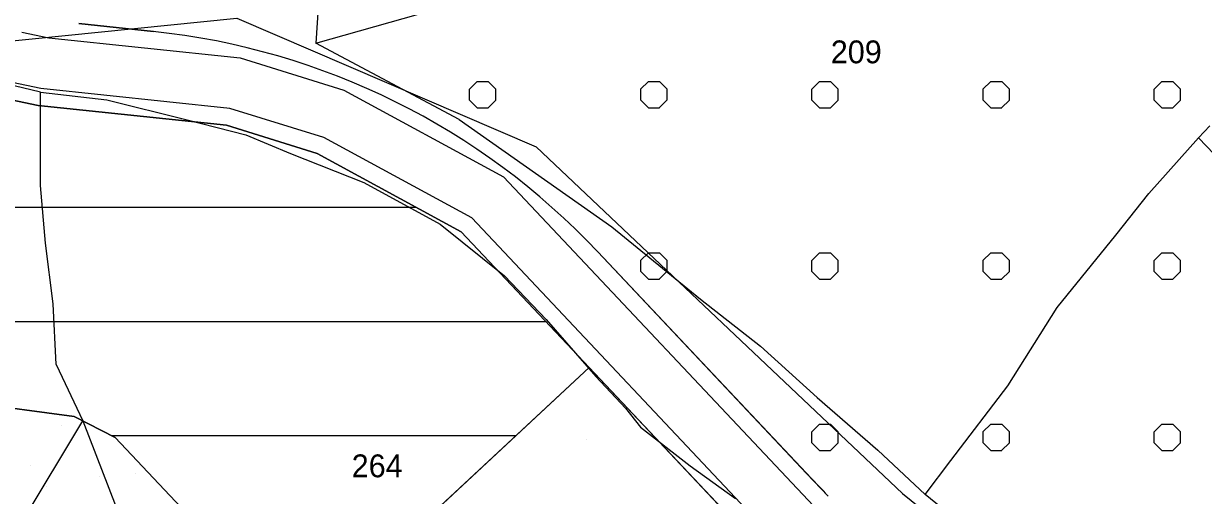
# Model space of a CAD drawing. Extents: x 410727 to 412947, y 4463506 to 4466382.
# Drawn here: x 411364.1 to 411570.9, y 4465926.9 to 4466009.6 of the extents above; entities that cross this region are included whole.
import ezdxf

# ---------------------------------------------------------------- set-up
doc = ezdxf.new("R2010")
doc.units = 0
for name, color, linetype in [('ADAKENARI', 7, 'Continuous'), ('F_ADAKENARI', 7, 'Continuous'), ('KALDIRIM', 7, 'Continuous'), ('KDS_PARSEL_NO', 7, 'Continuous'), ('KDS_PL', 7, 'Continuous'), ('PL_AYA_PARK_DINLENME', 7, 'Continuous'), ('PL_K_BHA', 7, 'Continuous'), ('PL_KA_TARIM_OZEL', 7, 'Continuous'), ('PL_KON_ONE_50', 7, 'Continuous'), ('TR_GELİŞME_KONUT_ÇOKAZ', 7, 'Continuous'), ('TR_OZELMAHSUL', 7, 'Continuous'), ('TR_PARKALANI', 7, 'Continuous'), ('TR_SU_DEPOSU', 7, 'Continuous'), ('Yerlesime_uygunluk_sınırı', 7, 'Continuous')]:
    doc.layers.add(name, color=color, linetype=linetype)

msp = doc.modelspace()

# ---------------------------------------------------------------- linework, layer by layer
at = {"layer": 'ADAKENARI'}
for p, q in [((411386.88, 4466008.2), (411373.8, 4466009.57)), ((411505.14, 4465926.77), (411464.76, 4465969.61)), ((411412.85, 4465902.41), (411463.26, 4465949.34)), ((411463.26, 4465949.34), (411496.15, 4465914.44))]:
    msp.add_line(p, q, dxfattribs=at)
for points in [[(411325.67, 4466003.81), (411366.7, 4465995.24), (411399.69, 4465991.77), (411415.6, 4465986.82), (411440.85, 4465973.12), (411463.26, 4465949.34), (411412.85, 4465902.41), (411380.18, 4465937.08), (411373.01, 4465940.76), (411281.5, 4465952.98)], [(411281.5, 4465952.98), (411373.01, 4465940.76), (411380.18, 4465937.08), (411412.85, 4465902.41), (411451.16, 4465861.77), (411442.37, 4465858.17), (411426.7, 4465854.46), (411405.75, 4465854.06), (411401.9, 4465854.15), (411393, 4465870.75), (411383.75, 4465887.97), (411383, 4465892.12), (411309.34, 4465895.53)]]:
    msp.add_lwpolyline(points, dxfattribs=at)
msp.add_arc((411373.79, 4465883.88), 125, 43.3014, 83.991, dxfattribs=at)
msp.add_arc((411373.79, 4465883.88), 125, 43.3014, 83.991, dxfattribs=at)
at = {"layer": 'F_ADAKENARI'}
msp.add_line((411501.36, 4465930.78), (411504.52, 4465927.56), dxfattribs=at)
at = {"layer": 'KALDIRIM'}
for points in [[(411363.84, 4466008.09), (411368.56, 4466007.11), (411402.12, 4466003.58), (411420.29, 4465997.93), (411448.26, 4465982.75), (411504.51, 4465923.06), (411515.54, 4465913.29), (411544.92, 4465897.92), (411576.35, 4465881.49), (411596.27, 4465871.64)], [(411400.3, 4465994.72), (411367.17, 4465998.21), (411362.15, 4465999.25)], [(411592.71, 4465863.36), (411572.27, 4465873.46), (411540.75, 4465889.95), (411510.4, 4465905.83), (411498.24, 4465916.59), (411442.7, 4465975.53), (411416.77, 4465989.6), (411400.3, 4465994.72)]]:
    msp.add_lwpolyline(points, dxfattribs=at)
at = {"layer": 'KDS_PL'}
for p, q in [((411416.72, 4466025.78), (411415.34, 4466006.12)), ((411415.34, 4466006.12), (411480.34, 4466024.59)), ((411440.45, 4465992.75), (411415.34, 4466006.12)), ((411367.09, 4465997.59), (411346.01, 4466002.57)), ((411367.09, 4465989.58), (411367.09, 4465997.59)), ((411367.09, 4465997.59), (411378.73, 4465996.2)), ((411378.73, 4465996.2), (411392.81, 4465992.71)), ((411392.81, 4465992.71), (411403.07, 4465990.1)), ((411440.45, 4465992.75), (411467.22, 4465973.97)), ((411572.03, 4465991.69), (411570.05, 4465989.57)), ((411367.09, 4465981.22), (411367.09, 4465989.58)), ((411403.07, 4465990.1), (411410.89, 4465986.79)), ((411561.37, 4465979.79), (411570.05, 4465989.57)), ((411570.05, 4465989.57), (411581.8, 4465977.25)), ((411410.89, 4465986.79), (411423.75, 4465981.74)), ((411367.96, 4465971.12), (411367.09, 4465981.22)), ((411423.75, 4465981.74), (411437.14, 4465974.43)), ((411555.59, 4465972.54), (411561.37, 4465979.79)), ((411437.14, 4465974.43), (411448.43, 4465965.37)), ((411467.22, 4465973.97), (411482.8, 4465961.32)), ((411545.28, 4465959.86), (411555.59, 4465972.54)), ((411369.35, 4465960.49), (411367.96, 4465971.12)), ((411448.43, 4465965.37), (411455.73, 4465957.71)), ((411369.87, 4465949.87), (411369.35, 4465960.49)), ((411482.8, 4465961.32), (411493.29, 4465953.05)), ((411536.61, 4465946.1), (411545.28, 4465959.86)), ((411455.73, 4465957.71), (411464.42, 4465947.78)), ((411493.29, 4465953.05), (411503.21, 4465944.09)), ((411369.87, 4465949.87), (411374.5, 4465940)), ((411464.42, 4465947.78), (411469.64, 4465942.21)), ((411526.67, 4465933.06), (411536.61, 4465946.1)), ((411503.21, 4465944.09), (411513.84, 4465934.84)), ((411469.64, 4465942.21), (411472.25, 4465938.9)), ((411362.5, 4465919.97), (411374.5, 4465940)), ((411374.5, 4465940), (411385, 4465913)), ((411472.25, 4465938.9), (411480.94, 4465932.11)), ((411513.84, 4465934.84), (411522.15, 4465927.08)), ((411480.94, 4465932.11), (411488.93, 4465926.36)), ((411522.15, 4465927.08), (411526.67, 4465933.06)), ((411528.65, 4465921.83), (411522.15, 4465927.08))]:
    msp.add_line(p, q, dxfattribs=at)
at = {"layer": 'PL_AYA_PARK_DINLENME'}
msp.add_lwpolyline([(411309.34, 4465895.53), (411383, 4465892.12), (411383.75, 4465887.97), (411393, 4465870.75), (411401.9, 4465854.15), (411405.75, 4465854.06), (411426.7, 4465854.46), (411442.37, 4465858.17), (411451.16, 4465861.77), (411412.85, 4465902.41), (411380.18, 4465937.08), (411373.01, 4465940.76), (411281.5, 4465952.98)], dxfattribs=at)
at = {"layer": 'PL_K_BHA'}
msp.add_lwpolyline([(411412.85, 4465902.41), (411451.16, 4465861.77), (411460.91, 4465866.67), (411472.17, 4465873.35), (411480.69, 4465879.01), (411489.78, 4465886.25), (411496.33, 4465891.98), (411503.64, 4465898.27), (411508.68, 4465903.34), (411496.15, 4465914.44), (411463.26, 4465949.34), (411412.85, 4465902.41)], dxfattribs=at)
at = {"layer": 'PL_KA_TARIM_OZEL'}
for points in [[(411373.8, 4466009.57), (411386.88, 4466008.2)], [(411464.76, 4465969.61), (411501.36, 4465930.78), (411505.14, 4465926.77)]]:
    msp.add_lwpolyline(points, dxfattribs=at)
msp.add_arc((411373.79, 4465883.88), 125, 43.3014, 83.991, dxfattribs=at)
at = {"layer": 'PL_KON_ONE_50'}
msp.add_lwpolyline([(411281.5, 4465952.98), (411373.01, 4465940.76), (411380.18, 4465937.08), (411412.85, 4465902.41), (411463.26, 4465949.34), (411440.85, 4465973.12), (411415.6, 4465986.82), (411399.69, 4465991.77), (411366.7, 4465995.24), (411325.67, 4466003.81)], dxfattribs=at)
at = {"layer": 'TR_GELİŞME_KONUT_ÇOKAZ'}
for p, q in [((411093.29, 4465977.39), (411432.99, 4465977.39)), ((411190.49, 4465957.39), (411455.67, 4465957.39)), ((411379.58, 4465937.39), (411450.42, 4465937.39))]:
    msp.add_line(p, q, dxfattribs=at)
msp.add_lwpolyline([(411281.5, 4465952.98), (411373.01, 4465940.76), (411380.18, 4465937.08), (411412.85, 4465902.41), (411463.26, 4465949.34), (411440.85, 4465973.12), (411415.6, 4465986.82), (411399.69, 4465991.77), (411366.7, 4465995.24), (411325.67, 4466003.81)], dxfattribs=at)
at = {"layer": 'TR_OZELMAHSUL'}
for p, q in [((411442.28, 4465998.06), (411443.63, 4465999.42)), ((411443.64, 4465999.42), (411445.56, 4465999.42)), ((411446.91, 4465998.07), (411445.56, 4465999.42)), ((411472.28, 4465998.06), (411473.63, 4465999.42)), ((411473.64, 4465999.42), (411475.56, 4465999.42)), ((411476.91, 4465998.07), (411475.56, 4465999.42)), ((411502.28, 4465998.06), (411503.63, 4465999.41)), ((411503.64, 4465999.42), (411505.56, 4465999.42)), ((411506.91, 4465998.07), (411505.56, 4465999.42)), ((411532.28, 4465998.06), (411533.63, 4465999.41)), ((411533.64, 4465999.42), (411535.56, 4465999.42)), ((411536.91, 4465998.07), (411535.56, 4465999.42)), ((411562.28, 4465998.06), (411563.63, 4465999.41)), ((411563.64, 4465999.42), (411565.56, 4465999.42)), ((411566.91, 4465998.07), (411565.56, 4465999.42)), ((411442.29, 4465996.15), (411442.29, 4465998.07)), ((411446.91, 4465996.15), (411446.91, 4465998.07)), ((411472.29, 4465996.15), (411472.29, 4465998.07)), ((411476.91, 4465996.15), (411476.91, 4465998.07)), ((411502.29, 4465996.15), (411502.29, 4465998.07)), ((411506.91, 4465996.15), (411506.91, 4465998.07)), ((411532.29, 4465996.15), (411532.29, 4465998.07)), ((411536.91, 4465996.15), (411536.91, 4465998.07)), ((411562.29, 4465996.15), (411562.29, 4465998.07)), ((411566.91, 4465996.15), (411566.91, 4465998.07)), ((411443.64, 4465994.8), (411442.29, 4465996.15)), ((411445.55, 4465994.79), (411446.9, 4465996.15)), ((411473.64, 4465994.8), (411472.29, 4465996.15)), ((411475.55, 4465994.79), (411476.9, 4465996.15)), ((411503.64, 4465994.8), (411502.29, 4465996.15)), ((411505.55, 4465994.79), (411506.9, 4465996.14)), ((411533.64, 4465994.8), (411532.29, 4465996.15)), ((411535.55, 4465994.79), (411536.9, 4465996.14)), ((411563.64, 4465994.8), (411562.29, 4465996.15)), ((411565.55, 4465994.79), (411566.9, 4465996.14)), ((411443.64, 4465994.8), (411445.56, 4465994.8)), ((411473.64, 4465994.8), (411475.56, 4465994.8)), ((411503.64, 4465994.8), (411505.56, 4465994.8)), ((411533.64, 4465994.8), (411535.56, 4465994.8)), ((411563.64, 4465994.8), (411565.56, 4465994.8)), ((411472.28, 4465968.06), (411473.63, 4465969.42)), ((411473.64, 4465969.42), (411475.56, 4465969.42)), ((411476.91, 4465968.07), (411475.56, 4465969.42)), ((411502.28, 4465968.06), (411503.63, 4465969.41)), ((411503.64, 4465969.42), (411505.56, 4465969.42)), ((411506.91, 4465968.07), (411505.56, 4465969.42)), ((411532.28, 4465968.06), (411533.63, 4465969.41)), ((411533.64, 4465969.42), (411535.56, 4465969.42)), ((411536.91, 4465968.07), (411535.56, 4465969.42)), ((411562.28, 4465968.06), (411563.63, 4465969.41)), ((411563.64, 4465969.42), (411565.56, 4465969.42)), ((411566.91, 4465968.07), (411565.56, 4465969.42)), ((411472.29, 4465966.15), (411472.29, 4465968.07)), ((411476.91, 4465966.15), (411476.91, 4465968.07)), ((411502.29, 4465966.15), (411502.29, 4465968.07)), ((411506.91, 4465966.15), (411506.91, 4465968.07)), ((411532.29, 4465966.15), (411532.29, 4465968.07)), ((411536.91, 4465966.15), (411536.91, 4465968.07)), ((411562.29, 4465966.15), (411562.29, 4465968.07)), ((411566.91, 4465966.15), (411566.91, 4465968.07)), ((411473.64, 4465964.8), (411472.29, 4465966.15)), ((411473.64, 4465964.8), (411475.56, 4465964.8)), ((411475.55, 4465964.79), (411476.9, 4465966.15)), ((411503.64, 4465964.8), (411502.29, 4465966.15)), ((411503.64, 4465964.8), (411505.56, 4465964.8)), ((411505.55, 4465964.79), (411506.9, 4465966.14)), ((411533.64, 4465964.8), (411532.29, 4465966.15)), ((411533.64, 4465964.8), (411535.56, 4465964.8)), ((411535.55, 4465964.79), (411536.9, 4465966.14)), ((411563.64, 4465964.8), (411562.29, 4465966.15)), ((411563.64, 4465964.8), (411565.56, 4465964.8)), ((411565.55, 4465964.79), (411566.9, 4465966.14)), ((411502.28, 4465938.06), (411503.63, 4465939.41)), ((411503.64, 4465939.42), (411505.56, 4465939.42)), ((411506.91, 4465938.07), (411505.56, 4465939.42)), ((411532.28, 4465938.06), (411533.63, 4465939.41)), ((411533.64, 4465939.42), (411535.56, 4465939.42)), ((411536.91, 4465938.07), (411535.56, 4465939.42)), ((411562.28, 4465938.06), (411563.63, 4465939.41)), ((411563.64, 4465939.42), (411565.56, 4465939.42)), ((411566.91, 4465938.07), (411565.56, 4465939.42)), ((411502.29, 4465936.15), (411502.29, 4465938.07)), ((411506.91, 4465936.15), (411506.91, 4465938.07)), ((411532.29, 4465936.15), (411532.29, 4465938.07)), ((411536.91, 4465936.15), (411536.91, 4465938.07)), ((411562.29, 4465936.15), (411562.29, 4465938.07)), ((411566.91, 4465936.15), (411566.91, 4465938.07)), ((411503.64, 4465934.8), (411502.29, 4465936.15)), ((411505.55, 4465934.79), (411506.9, 4465936.14)), ((411533.64, 4465934.8), (411532.29, 4465936.15)), ((411535.55, 4465934.79), (411536.9, 4465936.14)), ((411563.64, 4465934.8), (411562.29, 4465936.15)), ((411565.55, 4465934.79), (411566.9, 4465936.14)), ((411503.64, 4465934.8), (411505.56, 4465934.8)), ((411533.64, 4465934.8), (411535.56, 4465934.8)), ((411563.64, 4465934.8), (411565.56, 4465934.8))]:
    msp.add_line(p, q, dxfattribs=at)
at = {"layer": 'TR_PARKALANI'}
for p, q in [((411370.75, 4465939.13), (411370.75, 4465939.13)), ((411370.75, 4465939.13), (411370.75, 4465939.13)), ((411365.43, 4465932.11), (411365.43, 4465932.11)), ((411377.41, 4465930.15), (411377.41, 4465930.15)), ((411377.41, 4465930.15), (411377.41, 4465930.15)), ((411383.83, 4465930.72), (411383.83, 4465930.72)), ((411368.19, 4465928.41), (411368.19, 4465928.41))]:
    msp.add_line(p, q, dxfattribs=at)
at = {"layer": 'TR_SU_DEPOSU'}
msp.add_line((411462.85, 4465936.77), (411462.85, 4465936.77), dxfattribs=at)
at = {"layer": 'Yerlesime_uygunluk_sınırı'}
msp.add_lwpolyline([(411367.59, 4466324.54), (411367.57, 4466324.45), (411365.4, 4466317.37), (411329.85, 4466256.4), (411327.98, 4466256.94), (411298.02, 4466265.64), (411235.39, 4466203.01), (411292.89, 4466117.8), (411249.96, 4466080.27), (411288.76, 4466053.15), (411335.49, 4466003.87), (411401.49, 4466010.55), (411454, 4465988), (411518.19, 4465927.25), (411576.49, 4465880.17), (411546.8, 4465853.02), (411462.76, 4465826.95), (411417.87, 4465818.6), (411360.95, 4465816.44), (411257.66, 4465822.32), (411198.74, 4465810.19), (411081.53, 4465694.24)], dxfattribs=at)

# ---------------------------------------------------------------- texts
at = {"layer": 'KDS_PARSEL_NO'}
for s, p in [('209', (411505.61, 4466002.62)), ('264', (411421.64, 4465930.1))]:
    msp.add_text(s, height=4, dxfattribs=at).set_placement(p)

doc.saveas('drawing.dxf')
